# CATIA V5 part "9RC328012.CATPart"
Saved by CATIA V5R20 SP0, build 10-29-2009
Part number: 9RC328012
Revision: ANY
Definition: UNKNOWN
Nomenclature: 9RC328012
Source: Unknown
Bounding box of the stored display mesh (mm): x -64.6 to 16, y -16 to 16, z -5.85 to 5.85
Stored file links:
  C:\Users\Utente\Desktop\IO LAVORO\3D X SITO CF\CUMSA\3D files RC\RC 328012\9RC328012.CATPart
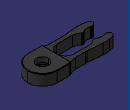
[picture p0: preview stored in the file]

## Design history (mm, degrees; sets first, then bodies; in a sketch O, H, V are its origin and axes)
Body1 "Chaflán1" (main body)
  Solid1: solid without history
